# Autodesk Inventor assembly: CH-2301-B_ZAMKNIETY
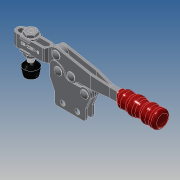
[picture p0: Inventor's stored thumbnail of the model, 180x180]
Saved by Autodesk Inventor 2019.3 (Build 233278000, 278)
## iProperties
Company: Î¢ÈíÖÐ¹ú
Created: 2012-09
Part Number: CH-2301-B_ZAMKNIETY
Material: Ogólny
Description: STEP AP203
Document SubType Name: Assembly
Designer: CADENGINEERING4
Sending System: SolidWorks 2010
Preprocessor: SwSTEP 2.0
Title: CH-2301-B.STEP
Author: Î¢ÈíÓÃ»§
Revision Number: ÈÎºÎ
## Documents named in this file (10)
- E:\STRONA\Horizontal toggle clamp\CH-2301-B\CH-2301-B_ZAMKNIETY.iam
- E:\STRONA\Horizontal toggle clamp\CH-2301-B\CH-2301-B-02___.ipt
- E:\STRONA\Horizontal toggle clamp\CH-2301-B\CH-2300-05____1.ipt
- E:\STRONA\Horizontal toggle clamp\CH-2301-B\FW100____1.ipt
- E:\STRONA\Horizontal toggle clamp\CH-2301-B\CH-2301-B-01___.ipt
- E:\STRONA\Horizontal toggle clamp\CH-2301-B\CH-2300-06___.ipt
- E:\STRONA\Horizontal toggle clamp\CH-2301-B\CH-FC-10138____1.ipt
- E:\STRONA\Horizontal toggle clamp\CH-2301-B\CH-2300-03____1.ipt
- E:\STRONA\Horizontal toggle clamp\CH-2301-B\10138-02____1.ipt
- E:\STRONA\Horizontal toggle clamp\CH-2301-B\CH-2300-04____1.ipt
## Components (14 placed, 14 different names)
1. CH-2301-B-02____1 — Zestawiające:1, Kątowe:1, Zestawiające:20, Zestawiające:21, Zestawiające:22, Zestawiające:23, Zestawiające:24, Zestawiające:25, Zestawiające:29
2. CH-2300-05____1_2 — Zestawiające:23, Zestawiające:26
3. CH-2300-05____1_3 — Zestawiające:12, Zestawiające:13
4. FW100____1_4 — Zestawiające:2, Równoległe:1, Zestawiające:17, Zestawiające:18, Zestawiające:20
5. FW100____1_5 — Równoległe:1, Zestawiające:14, Zestawiające:16, Zestawiające:21
6. CH-2301-B-01____6 — Zestawiające:6, Zestawiające:7, Zestawiające:8, Zestawiające:9, Zestawiające:24, Zestawiające:25, Zestawiające:26, Przejściowe:1
7. CH-2300-05____1_7 — Zestawiające:27, Zestawiające:28, Zestawiające:29
8. CH-2300-06____8 — Zestawiające:3, Zestawiające:4, Zestawiające:5
9. CH-FC-10138____1_9 — Równoległe:2, Zestawiające:14, Zestawiające:15, Zestawiające:17, Zestawiające:19, Zestawiające:22
10. CH-2300-05____1_10 — Zestawiające:8, Zestawiające:9
11. CH-2300-03____1_11 — Zestawiające:3, Zestawiające:4, Zestawiające:5, Zestawiające:10, Zestawiające:11, Zestawiające:12, Zestawiające:13, Zestawiające:27, Zestawiające:28, Przejściowe:1
12. 10138-02____1_12 — Równoległe:2, Zestawiające:18, Zestawiające:19
13. CH-2300-04____1_13 — Zestawiające:6, Zestawiające:7, Zestawiające:10, Zestawiające:11
14. 10138-02____1_14 — Zestawiające:15, Zestawiające:16
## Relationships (33: Mate 29, Flush 2, Angle 1, Transitional 1)
- Zestawiające:1 [Mate]: CH-2301-B-02____1
- Kątowe:1 [Angle]: CH-2301-B-02____1
- Zestawiające:2 [Mate]: FW100____1_4
- Równoległe:1 [Flush]: FW100____1_4 ↔ FW100____1_5
- Równoległe:2 [Flush]: CH-FC-10138____1_9 ↔ 10138-02____1_12
- Zestawiające:3 [Mate]: CH-2300-06____8 ↔ CH-2300-03____1_11
- Zestawiające:4 [Mate]: CH-2300-06____8 ↔ CH-2300-03____1_11
- Zestawiające:5 [Mate]: CH-2300-06____8 ↔ CH-2300-03____1_11
- Zestawiające:6 [Mate]: CH-2301-B-01____6 ↔ CH-2300-04____1_13
- Zestawiające:7 [Mate]: CH-2301-B-01____6 ↔ CH-2300-04____1_13
- Zestawiające:8 [Mate]: CH-2301-B-01____6 ↔ CH-2300-05____1_10
- Zestawiające:9 [Mate]: CH-2301-B-01____6 ↔ CH-2300-05____1_10
- Zestawiające:10 [Mate]: CH-2300-03____1_11 ↔ CH-2300-04____1_13
- Zestawiające:11 [Mate]: CH-2300-03____1_11 ↔ CH-2300-04____1_13
- Zestawiające:12 [Mate]: CH-2300-05____1_3 ↔ CH-2300-03____1_11
- Zestawiające:13 [Mate]: CH-2300-05____1_3 ↔ CH-2300-03____1_11
- Zestawiające:14 [Mate]: FW100____1_5 ↔ CH-FC-10138____1_9
- Zestawiające:15 [Mate]: CH-FC-10138____1_9 ↔ 10138-02____1_14
- Zestawiające:16 [Mate]: FW100____1_5 ↔ 10138-02____1_14
- Zestawiające:17 [Mate]: FW100____1_4 ↔ CH-FC-10138____1_9
- Zestawiające:18 [Mate]: FW100____1_4 ↔ 10138-02____1_12
- Zestawiające:19 [Mate]: CH-FC-10138____1_9 ↔ 10138-02____1_12
- Zestawiające:20 [Mate]: CH-2301-B-02____1 ↔ FW100____1_4
- Zestawiające:21 [Mate]: CH-2301-B-02____1 ↔ FW100____1_5
- Zestawiające:22 [Mate]: CH-2301-B-02____1 ↔ CH-FC-10138____1_9
- Zestawiające:23 [Mate]: CH-2301-B-02____1 ↔ CH-2300-05____1_2
- Zestawiające:24 [Mate]: CH-2301-B-02____1 ↔ CH-2301-B-01____6
- Zestawiające:25 [Mate]: CH-2301-B-02____1 ↔ CH-2301-B-01____6
- Zestawiające:26 [Mate]: CH-2300-05____1_2 ↔ CH-2301-B-01____6
- Zestawiające:27 [Mate]: CH-2300-05____1_7 ↔ CH-2300-03____1_11
- Zestawiające:28 [Mate]: CH-2300-05____1_7 ↔ CH-2300-03____1_11
- Zestawiające:29 [Mate]: CH-2301-B-02____1 ↔ CH-2300-05____1_7
- Przejściowe:1 [Transitional]: CH-2301-B-01____6 ↔ CH-2300-03____1_11
